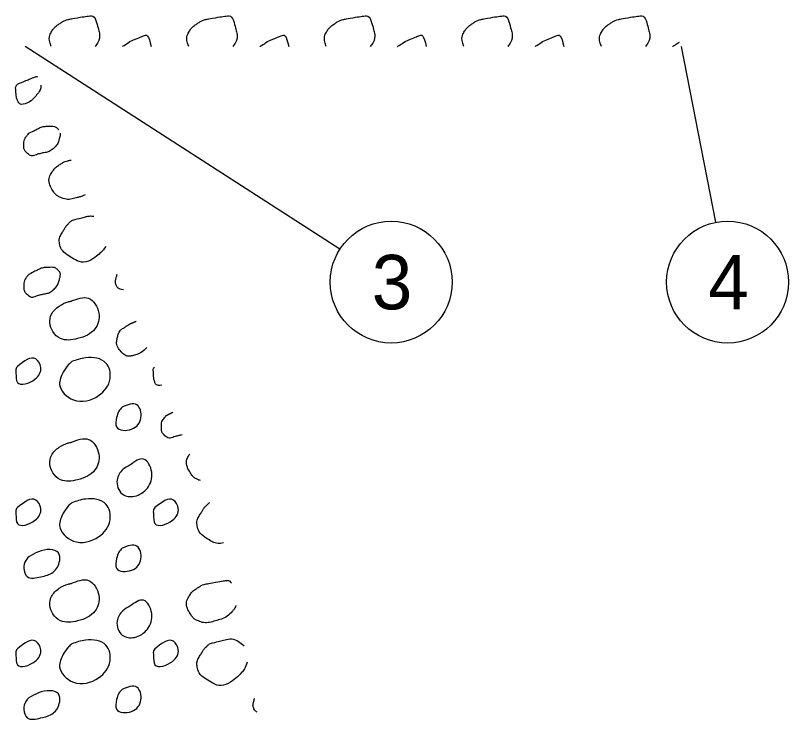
# Model space of a CAD drawing. Extents: x 0 to 340, y 0 to 220.
# Drawn here: x 150.51 to 170.38, y 131 to 149.04 of the extents above; entities that cross this region are included whole.
import ezdxf

# ---------------------------------------------------------------- set-up
doc = ezdxf.new("R2010")
doc.units = 0
for name, color, linetype in [('GE_P_Alignment_100_Stations', 7, 'Continuous'), ('MT_P_Work_Area', 7, 'Continuous'), ('SC_Scratch1', 7, 'Continuous')]:
    doc.layers.add(name, color=color, linetype=linetype)

msp = doc.modelspace()

# ---------------------------------------------------------------- linework, layer by layer
at = {"layer": 'GE_P_Alignment_100_Stations'}
for p, q in [((158.854, 143.024), (150.761, 148.239)), ((168.517, 143.714), (167.632, 148.239))]:
    msp.add_line(p, q, dxfattribs=at)
at = {"layer": 'MT_P_Work_Area'}
for centre in [(160.171, 142.176), (168.818, 142.176)]:
    msp.add_circle(centre, 1.567, dxfattribs=at)
at = {"layer": 'SC_Scratch1'}
for points, degree in [([(151.941, 148.945), (152.092, 148.971), (152.244, 149), (152.395, 149.021), (152.547, 149.042), (152.617, 148.783), (152.655, 148.641), (152.689, 148.514), (152.667, 148.358), (152.562, 148.239)], 3), ([(155.477, 148.945), (155.628, 148.971), (155.78, 149), (155.931, 149.021), (156.082, 149.042), (156.152, 148.783), (156.19, 148.641), (156.224, 148.514), (156.203, 148.358), (156.097, 148.239)], 3), ([(159.013, 148.945), (159.164, 148.971), (159.316, 149), (159.467, 149.021), (159.618, 149.042), (159.688, 148.783), (159.726, 148.641), (159.76, 148.514), (159.739, 148.358), (159.633, 148.239)], 3), ([(162.549, 148.945), (162.7, 148.971), (162.851, 149), (163.003, 149.021), (163.154, 149.042), (163.224, 148.783), (163.262, 148.641), (163.296, 148.514), (163.275, 148.358), (163.169, 148.239)], 3), ([(166.084, 148.945), (166.236, 148.971), (166.387, 149), (166.539, 149.021), (166.69, 149.042), (166.76, 148.783), (166.798, 148.641), (166.832, 148.514), (166.81, 148.358), (166.705, 148.239)], 3), ([(151.433, 148.239), (151.38, 148.361), (151.374, 148.504), (151.436, 148.608), (151.486, 148.692), (151.554, 148.766), (151.641, 148.821), (151.715, 148.868), (151.785, 148.912), (151.867, 148.93), (151.895, 148.935), (151.922, 148.941), (151.95, 148.947)], 3), ([(154.968, 148.239), (154.916, 148.361), (154.91, 148.504), (154.972, 148.608), (155.022, 148.692), (155.09, 148.766), (155.177, 148.821), (155.251, 148.868), (155.321, 148.912), (155.403, 148.93), (155.43, 148.935), (155.458, 148.941), (155.485, 148.947)], 3), ([(158.504, 148.239), (158.452, 148.361), (158.446, 148.504), (158.508, 148.608), (158.558, 148.692), (158.626, 148.766), (158.713, 148.821), (158.787, 148.868), (158.857, 148.912), (158.939, 148.93), (158.966, 148.935), (158.994, 148.941), (159.021, 148.947)], 3), ([(162.04, 148.239), (161.988, 148.361), (161.982, 148.504), (162.044, 148.608), (162.094, 148.692), (162.162, 148.766), (162.249, 148.821), (162.322, 148.868), (162.393, 148.912), (162.474, 148.93), (162.502, 148.935), (162.529, 148.941), (162.557, 148.947)], 3), ([(165.576, 148.239), (165.524, 148.361), (165.517, 148.504), (165.579, 148.608), (165.629, 148.692), (165.697, 148.766), (165.784, 148.821), (165.858, 148.868), (165.929, 148.912), (166.01, 148.93), (166.038, 148.935), (166.065, 148.941), (166.093, 148.947)], 3), ([(153.457, 148.363), (153.574, 148.413), (153.691, 148.463), (153.809, 148.514), (153.912, 148.558), (153.97, 148.372), (154.002, 148.239)], 3), ([(156.993, 148.363), (157.11, 148.413), (157.227, 148.463), (157.344, 148.514), (157.448, 148.558), (157.506, 148.372), (157.538, 148.239)], 3), ([(160.529, 148.363), (160.646, 148.413), (160.763, 148.463), (160.88, 148.514), (160.984, 148.558), (161.042, 148.372), (161.074, 148.239)], 3), ([(164.064, 148.363), (164.182, 148.413), (164.299, 148.463), (164.416, 148.514), (164.52, 148.558), (164.578, 148.372), (164.609, 148.239)], 3), ([(153.266, 148.239), (153.268, 148.24), (153.27, 148.242), (153.273, 148.244), (153.334, 148.284), (153.396, 148.323), (153.457, 148.363)], 3), ([(156.801, 148.239), (156.804, 148.24), (156.806, 148.242), (156.809, 148.244), (156.87, 148.284), (156.932, 148.323), (156.993, 148.363)], 3), ([(160.337, 148.239), (160.34, 148.24), (160.342, 148.242), (160.344, 148.244), (160.406, 148.284), (160.467, 148.323), (160.529, 148.363)], 3), ([(163.873, 148.239), (163.875, 148.24), (163.878, 148.242), (163.88, 148.244), (163.942, 148.284), (164.003, 148.323), (164.064, 148.363)], 3), ([(167.409, 148.239), (167.411, 148.24), (167.414, 148.242), (167.416, 148.244), (167.472, 148.281), (167.528, 148.316), (167.584, 148.352)], 3), ([(150.563, 147.268), (150.721, 147.332), (150.88, 147.4), (151.038, 147.46), (151.052, 147.466), (151.064, 147.464), (151.076, 147.459)], 3), ([(151.164, 147.241), (151.173, 147.142), (151.096, 147.038), (151.015, 146.94), (150.903, 146.805), (150.622, 146.708), (150.565, 146.855), (150.534, 146.934), (150.529, 147.014), (150.525, 147.095), (150.524, 147.136), (150.509, 147.18), (150.53, 147.216), (150.54, 147.235), (150.552, 147.251), (150.563, 147.268)], 3), ([(150.855, 146.004), (150.938, 146.046), (151.021, 146.088), (151.105, 146.129), (151.196, 146.175), (151.306, 146.184), (151.405, 146.187), (151.479, 146.189), (151.55, 146.171), (151.616, 146.106), (151.62, 146.102), (151.624, 146.098), (151.627, 146.094)], 3), ([(151.663, 146.006), (151.666, 145.971), (151.659, 145.934), (151.65, 145.902), (151.621, 145.797), (151.582, 145.691), (151.48, 145.606), (151.379, 145.523), (151.274, 145.511), (151.166, 145.486), (151.054, 145.46), (150.925, 145.393), (150.815, 145.492), (150.742, 145.557), (150.727, 145.633), (150.729, 145.707), (150.73, 145.774), (150.739, 145.852), (150.78, 145.907), (150.805, 145.94), (150.83, 145.972), (150.855, 146.004)], 3), ([(152.303, 144.42), (152.242, 144.392), (152.178, 144.371), (152.112, 144.352), (151.971, 144.31), (151.813, 144.295), (151.672, 144.354), (151.587, 144.39), (151.525, 144.452), (151.473, 144.532), (151.386, 144.666), (151.361, 144.851), (151.436, 144.977), (151.486, 145.061), (151.554, 145.135), (151.641, 145.191), (151.715, 145.238), (151.785, 145.282), (151.867, 145.299), (151.892, 145.304), (151.917, 145.31), (151.942, 145.315)], 3), ([(151.941, 145.315), (151.941, 145.315), (151.942, 145.315), (151.942, 145.315)], 2), ([(151.962, 143.763), (152.081, 143.795), (152.199, 143.826), (152.318, 143.857), (152.387, 143.874), (152.456, 143.88), (152.525, 143.872)], 3), ([(152.838, 143.095), (152.789, 143.022), (152.726, 142.952), (152.65, 142.887), (152.46, 142.725), (152.196, 142.661), (152.002, 142.777), (151.844, 142.87), (151.678, 143.01), (151.648, 143.175), (151.629, 143.278), (151.682, 143.397), (151.743, 143.493), (151.786, 143.562), (151.824, 143.631), (151.881, 143.686), (151.908, 143.712), (151.935, 143.738), (151.962, 143.763)], 3), ([(150.855, 142.374), (150.938, 142.415), (151.021, 142.457), (151.105, 142.499), (151.196, 142.544), (151.306, 142.553), (151.405, 142.556), (151.479, 142.558), (151.55, 142.541), (151.616, 142.475), (151.677, 142.415), (151.668, 142.335), (151.65, 142.272), (151.621, 142.167), (151.582, 142.06), (151.48, 141.975), (151.379, 141.892), (151.274, 141.88), (151.166, 141.855), (151.054, 141.829), (150.925, 141.762), (150.815, 141.861), (150.742, 141.926), (150.727, 142.002), (150.729, 142.077), (150.73, 142.143), (150.739, 142.222), (150.78, 142.277), (150.805, 142.31), (150.83, 142.341), (150.855, 142.374)], 3), ([(153.291, 141.975), (153.214, 141.984), (153.143, 142.018), (153.112, 142.08), (153.074, 142.158), (153.093, 142.248), (153.115, 142.326), (153.119, 142.343), (153.123, 142.361), (153.128, 142.379)], 3), ([(153.89, 140.492), (153.794, 140.384), (153.685, 140.331), (153.571, 140.297), (153.475, 140.268), (153.354, 140.263), (153.26, 140.356), (153.147, 140.469), (153.104, 140.601), (153.127, 140.715), (153.145, 140.806), (153.188, 140.926), (153.273, 140.983), (153.334, 141.024), (153.396, 141.062), (153.457, 141.102)], 3), ([(153.457, 141.102), (153.51, 141.125), (153.563, 141.147), (153.616, 141.17)], 2), ([(154.28, 139.525), (154.199, 139.511), (154.127, 139.527), (154.1, 139.594), (154.07, 139.673), (154.064, 139.754), (154.061, 139.834), (154.06, 139.875), (154.044, 139.919), (154.065, 139.955), (154.073, 139.969), (154.082, 139.982), (154.091, 139.994)], 3), ([(154.797, 138.246), (154.765, 138.238), (154.734, 138.232), (154.702, 138.225), (154.589, 138.199), (154.46, 138.132), (154.35, 138.231), (154.278, 138.296), (154.263, 138.372), (154.264, 138.446), (154.266, 138.513), (154.274, 138.591), (154.316, 138.646), (154.341, 138.679), (154.365, 138.711), (154.39, 138.743)], 3), ([(154.39, 138.743), (154.447, 138.772), (154.504, 138.8), (154.561, 138.829)], 2), ([(155.271, 137.072), (155.25, 137.077), (155.229, 137.084), (155.208, 137.093), (155.122, 137.129), (155.06, 137.191), (155.009, 137.271), (154.922, 137.405), (154.896, 137.59), (154.972, 137.716), (154.979, 137.729), (154.987, 137.741), (154.996, 137.753)], 3), ([(155.86, 135.466), (155.747, 135.445), (155.634, 135.459), (155.538, 135.516), (155.38, 135.609), (155.214, 135.749), (155.184, 135.914), (155.165, 136.017), (155.218, 136.136), (155.279, 136.232), (155.322, 136.301), (155.36, 136.37), (155.417, 136.425), (155.444, 136.451), (155.471, 136.477), (155.498, 136.502)], 3), ([(155.498, 136.502), (155.499, 136.503), (155.5, 136.503), (155.501, 136.503)], 2), ([(156.181, 133.858), (156.162, 133.807), (156.134, 133.757), (156.094, 133.713), (155.96, 133.565), (155.812, 133.508), (155.648, 133.46), (155.507, 133.419), (155.348, 133.403), (155.208, 133.463), (155.122, 133.499), (155.06, 133.561), (155.009, 133.641), (154.922, 133.775), (154.896, 133.959), (154.972, 134.086), (155.022, 134.17), (155.09, 134.244), (155.177, 134.299), (155.251, 134.346), (155.321, 134.39), (155.403, 134.408), (155.43, 134.413), (155.458, 134.419), (155.485, 134.425)], 3), ([(155.477, 134.423), (155.628, 134.449), (155.78, 134.478), (155.931, 134.499), (155.986, 134.507), (156.031, 134.477), (156.067, 134.43)], 3), ([(155.498, 132.872), (155.616, 132.903), (155.735, 132.934), (155.854, 132.965), (156.027, 133.01), (156.201, 132.978), (156.374, 132.833), (156.379, 132.83), (156.383, 132.826), (156.387, 132.822)], 3), ([(156.472, 132.398), (156.423, 132.253), (156.327, 132.117), (156.186, 131.996), (155.996, 131.834), (155.732, 131.77), (155.538, 131.885), (155.38, 131.978), (155.214, 132.118), (155.184, 132.283), (155.165, 132.386), (155.218, 132.506), (155.279, 132.602), (155.322, 132.67), (155.36, 132.739), (155.417, 132.794), (155.444, 132.82), (155.471, 132.846), (155.498, 132.872)], 3), ([(156.728, 131.112), (156.693, 131.129), (156.664, 131.155), (156.648, 131.189), (156.61, 131.267), (156.629, 131.357), (156.65, 131.435), (156.653, 131.444), (156.655, 131.454), (156.658, 131.464)], 3)]:
    msp.add_open_spline(points, degree=degree, dxfattribs=at)
for points in [[(151.941, 141.684), (152.395, 141.76), (152.655, 141.38), (152.558, 140.974), (152.112, 140.721), (151.672, 140.724), (151.473, 140.902), (151.436, 141.347), (151.641, 141.56), (151.867, 141.669), (151.95, 141.686)], [(150.563, 140.007), (151.038, 140.199), (151.164, 139.981), (151.015, 139.679), (150.565, 139.594), (150.525, 139.834), (150.53, 139.955), (150.563, 140.007)], [(151.962, 140.133), (152.318, 140.226), (152.839, 140.094), (152.946, 139.692), (152.65, 139.257), (152.002, 139.146), (151.648, 139.544), (151.743, 139.863), (151.881, 140.055), (151.962, 140.133)], [(153.253, 138.96), (153.635, 139.016), (153.739, 138.687), (153.499, 138.393), (153.112, 138.45), (153.115, 138.696), (153.173, 138.859), (153.253, 138.96)], [(151.941, 138.054), (152.395, 138.13), (152.655, 137.75), (152.558, 137.343), (152.112, 137.091), (151.672, 137.093), (151.473, 137.271), (151.436, 137.716), (151.641, 137.93), (151.867, 138.038), (151.95, 138.056)], [(153.457, 137.471), (153.809, 137.622), (154.016, 137.284), (153.905, 136.879), (153.571, 136.666), (153.26, 136.726), (153.127, 137.085), (153.273, 137.352), (153.457, 137.471)], [(150.563, 136.376), (151.038, 136.569), (151.164, 136.351), (151.015, 136.048), (150.565, 135.964), (150.525, 136.204), (150.53, 136.325), (150.563, 136.376)], [(151.962, 136.502), (152.318, 136.596), (152.839, 136.464), (152.946, 136.061), (152.65, 135.626), (152.002, 135.516), (151.648, 135.914), (151.743, 136.232), (151.881, 136.425), (151.962, 136.502)], [(154.099, 136.376), (154.574, 136.569), (154.699, 136.351), (154.55, 136.048), (154.1, 135.964), (154.061, 136.204), (154.065, 136.325), (154.099, 136.376)], [(153.253, 135.329), (153.635, 135.385), (153.739, 135.057), (153.499, 134.763), (153.112, 134.819), (153.115, 135.065), (153.173, 135.228), (153.253, 135.329)], [(150.855, 135.113), (151.105, 135.238), (151.405, 135.295), (151.616, 135.214), (151.65, 135.011), (151.48, 134.714), (151.166, 134.594), (150.815, 134.6), (150.729, 134.816), (150.78, 135.016), (150.855, 135.113)], [(151.941, 134.423), (152.395, 134.499), (152.655, 134.119), (152.558, 133.713), (152.112, 133.46), (151.672, 133.463), (151.473, 133.641), (151.436, 134.086), (151.641, 134.299), (151.867, 134.408), (151.95, 134.425)], [(153.457, 133.841), (153.809, 133.992), (154.016, 133.653), (153.905, 133.248), (153.571, 133.036), (153.26, 133.095), (153.127, 133.454), (153.273, 133.722), (153.457, 133.841)], [(150.563, 132.746), (151.038, 132.938), (151.164, 132.72), (151.015, 132.418), (150.565, 132.333), (150.525, 132.573), (150.53, 132.694), (150.563, 132.746)], [(151.962, 132.872), (152.318, 132.965), (152.839, 132.833), (152.946, 132.431), (152.65, 131.996), (152.002, 131.885), (151.648, 132.283), (151.743, 132.602), (151.881, 132.794), (151.962, 132.872)], [(154.099, 132.746), (154.574, 132.938), (154.699, 132.72), (154.55, 132.418), (154.1, 132.333), (154.061, 132.573), (154.065, 132.694), (154.099, 132.746)], [(153.253, 131.699), (153.635, 131.755), (153.739, 131.426), (153.499, 131.132), (153.112, 131.189), (153.115, 131.435), (153.173, 131.598), (153.253, 131.699)], [(150.855, 131.482), (151.105, 131.607), (151.405, 131.665), (151.616, 131.584), (151.65, 131.38), (151.48, 131.084), (151.166, 130.964), (150.815, 130.97), (150.729, 131.185), (150.78, 131.385), (150.855, 131.482)]]:
    msp.add_spline(points, degree=3, dxfattribs=at)

# ---------------------------------------------------------------- texts
at = {"layer": 'MT_P_Work_Area'}
for s, p in [('3', (159.672, 141.476)), ('4', (168.322, 141.476))]:
    msp.add_text(s, height=1.4, dxfattribs=at).set_placement(p)

doc.saveas('drawing.dxf')
